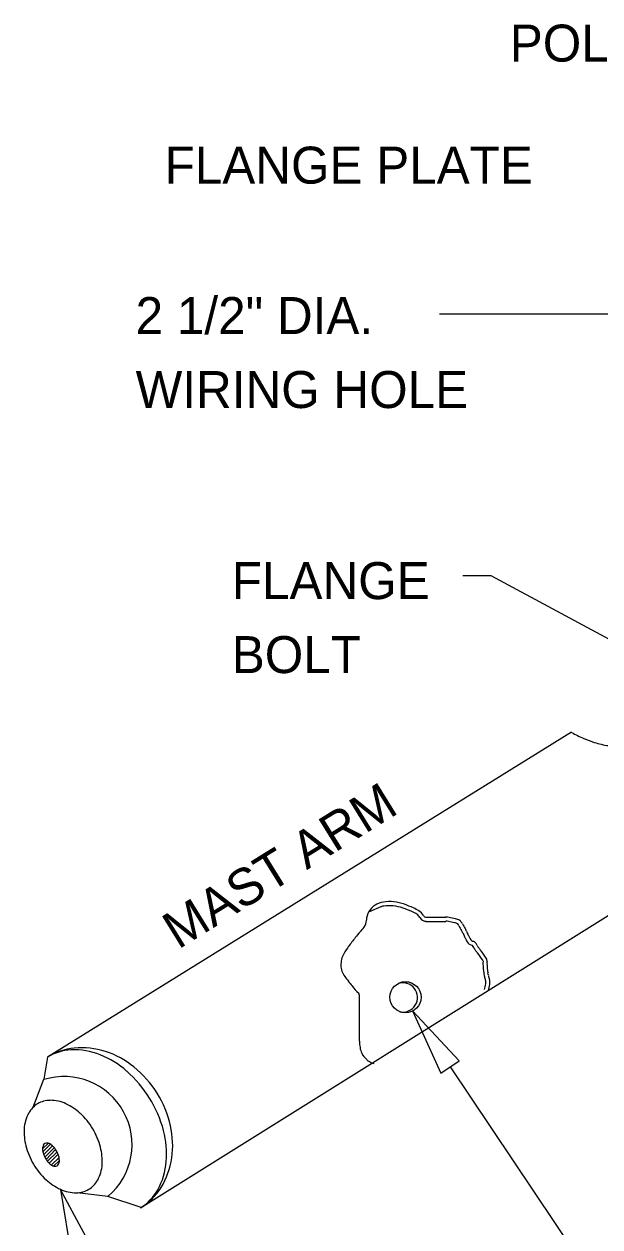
# Model space of a CAD drawing. Extents: x -1551.93 to -1544.71, y 2060.77 to 2070.61.
# Drawn here: x -1550.142 to -1549.207, y 2068.655 to 2070.606 of the extents above; entities that cross this region are included whole.
import ezdxf

# ---------------------------------------------------------------- set-up
doc = ezdxf.new("R2010")
doc.units = 0
for name, color, linetype in [('DETL-DIMS', 7, 'Continuous'), ('DETL-LINE', 7, 'Continuous'), ('DETL-NOTE', 7, 'Continuous')]:
    doc.layers.add(name, color=color, linetype=linetype)

msp = doc.modelspace()

# ---------------------------------------------------------------- linework, layer by layer
at = {"layer": 'DETL-DIMS'}
for p, q in [((-1549.1656, 2070.135), (-1549.4676, 2070.135)), ((-1549.3836, 2069.711), (-1549.4296, 2069.711)), ((-1549.0616, 2069.537), (-1549.3836, 2069.711)), ((-1549.4506, 2068.914), (-1549.2146, 2068.563))]:
    msp.add_line(p, q, dxfattribs=at)
for points in [[(-1549.4656, 2068.904), (-1549.4356, 2068.924), (-1549.5116, 2069.005)], [(-1550.0646, 2068.606), (-1550.0296, 2068.617), (-1550.0826, 2068.715)]]:
    msp.add_lwpolyline(points, close=True, dxfattribs=at)
at = {"layer": 'DETL-LINE'}
for p, q in [((-1549.2536, 2069.457), (-1550.1036, 2068.93)), ((-1549.1096, 2069.212), (-1549.9526, 2068.685)), ((-1549.5626, 2069.174), (-1549.5826, 2069.165)), ((-1550.1036, 2068.93), (-1550.1096, 2068.894)), ((-1550.1266, 2068.849), (-1550.1096, 2068.894)), ((-1550.1116, 2068.781), (-1550.1026, 2068.79)), ((-1550.1116, 2068.776), (-1550.0986, 2068.789)), ((-1550.1096, 2068.772), (-1550.0956, 2068.786)), ((-1550.1076, 2068.768), (-1550.0926, 2068.783)), ((-1550.1056, 2068.764), (-1550.0906, 2068.78)), ((-1550.1036, 2068.761), (-1550.0886, 2068.776)), ((-1550.1006, 2068.758), (-1550.0866, 2068.772)), ((-1550.0976, 2068.755), (-1550.0846, 2068.767)), ((-1550.0936, 2068.753), (-1550.0846, 2068.762)), ((-1550.0056, 2068.704), (-1550.0556, 2068.71)), ((-1549.9516, 2068.686), (-1550.0056, 2068.704))]:
    msp.add_line(p, q, dxfattribs=at)
for points in [[(-1549.4896, 2069.157), (-1549.4726, 2069.157), (-1549.4576, 2069.157)], [(-1549.4896, 2069.15), (-1549.4726, 2069.15), (-1549.4576, 2069.15)], [(-1549.5976, 2068.956), (-1549.5976, 2068.961), (-1549.5976, 2068.98), (-1549.5976, 2068.985), (-1549.5976, 2069.01), (-1549.5976, 2069.031)]]:
    msp.add_lwpolyline(points, dxfattribs=at)
msp.add_circle((-1549.5229, 2069.0271), 0.0253, dxfattribs=at)
for centre, radius, start, end in [((-1549.1315, 2069.6791), 0.2536, 241.2446, 246.3282), ((-1549.1681, 2069.5956), 0.1625, 246.3282, 252.6806), ((-1549.1724, 2069.5817), 0.1479, 252.6806, 261.7135), ((-1549.5542, 2069.149), 0.0328, 123.3386, 148.6731), ((-1549.5537, 2069.1482), 0.0337, 98.3447, 123.3386), ((-1549.5537, 2069.1482), 0.0272, 98.3447, 108.1148), ((-1549.549, 2069.1162), 0.0661, 83.8602, 98.3447), ((-1549.549, 2069.1162), 0.0595, 83.8602, 98.3447), ((-1549.55, 2069.1068), 0.069, 70.3238, 83.8602), ((-1549.55, 2069.1068), 0.0756, 70.3238, 83.8602), ((-1549.5911, 2068.9921), 0.1909, 65.6872, 70.3238), ((-1549.5911, 2068.9921), 0.1974, 65.6872, 70.3238), ((-1549.5419, 2069.1008), 0.0781, 58.3145, 65.6872), ((-1549.6046, 2069.1522), 0.0184, 322.1869, 0.0792), ((-1549.5596, 2069.1523), 0.0265, 148.673, 180.0792), ((-1549.5419, 2069.1008), 0.0716, 58.3145, 65.6872), ((-1549.5119, 2069.1495), 0.0143, 28.9026, 58.3145), ((-1549.5119, 2069.1495), 0.0208, 28.9026, 58.3145), ((-1549.4891, 2069.1621), 0.0118, 208.9026, 270.0637), ((-1549.4891, 2069.1621), 0.00519, 208.9026, 270.0637), ((-1549.4576, 2069.1229), 0.0341, 80.8176, 90.0637), ((-1549.4576, 2069.1229), 0.0275, 80.8176, 90.0637), ((-1549.4726, 2069.03), 0.1215, 76.0538, 80.8176), ((-1549.4726, 2069.03), 0.1281, 76.0538, 80.8176), ((-1549.4516, 2069.1147), 0.0409, 65.4401, 76.0538), ((-1549.4362, 2069.1483), 0.0039, 30.5819, 65.4401), ((-1549.5663, 2069.0714), 0.155, 28.7603, 30.5819), ((-1549.4492, 2068.9998), 0.1987, 137.8117, 141.3618), ((-1549.6934, 2069.2211), 0.1309, 317.8117, 322.1869), ((-1549.4516, 2069.1147), 0.0343, 66.8178, 76.0538), ((-1549.5663, 2069.0714), 0.1485, 28.7603, 30.254), ((-1549.0117, 2069.3758), 0.4842, 208.7603, 209.7981), ((-1547.4275, 2070.283), 2.3098, 209.7981, 209.8596), ((-1549.5096, 2069.0878), 0.091, 29.5607, 29.8596), ((-1549.0117, 2069.3758), 0.4776, 208.7603, 209.7981), ((-1549.4424, 2069.1259), 0.0138, 24.447, 29.5607), ((-1549.1654, 2069.2518), 0.2905, 204.447, 205.8161), ((-1547.4275, 2070.283), 2.3032, 209.7981, 209.8596), ((-1549.5096, 2069.0878), 0.0976, 29.5607, 29.8596), ((-1549.4424, 2069.1259), 0.0204, 24.447, 29.5607), ((-1549.1654, 2069.2518), 0.284, 204.447, 205.8161), ((-1549.3824, 2068.9464), 0.2842, 141.3618, 144.9095), ((-1549.2911, 2069.191), 0.1508, 205.8161, 207.7097), ((-1549.3289, 2069.1711), 0.1082, 207.7097, 209.9657), ((-1549.4124, 2069.123), 0.0118, 209.9657, 259.0294), ((-1549.2911, 2069.191), 0.1443, 205.8161, 207.7097), ((-1549.3289, 2069.1711), 0.1016, 207.7097, 209.9657), ((-1549.4124, 2069.123), 0.00521, 209.9657, 259.0294), ((-1549.4147, 2069.111), 0.000415, 36.9612, 79.0295), ((-1549.434, 2069.0965), 0.0246, 27.5853, 36.9612), ((-1549.4147, 2069.111), 0.00698, 36.9612, 79.0295), ((-1549.434, 2069.0965), 0.0311, 27.5853, 36.9612), ((-1549.5937, 2069.0802), 0.0339, 149.2046, 182.3774), ((-1549.4563, 2068.9983), 0.194, 144.9095, 149.2046), ((-1549.3843, 2069.1224), 0.0315, 207.5853, 218.0695), ((-1549.3264, 2069.1678), 0.1051, 218.0695, 219.1376), ((-1549.5933, 2068.9506), 0.2391, 38.4612, 39.1376), ((-1549.3843, 2069.1224), 0.0249, 207.5853, 218.0695), ((-1549.5332, 2068.9984), 0.1623, 33.1344, 38.4612), ((-1549.3264, 2069.1678), 0.0985, 218.0695, 219.1376), ((-1549.5933, 2068.9506), 0.2456, 38.4612, 39.1376), ((-1549.5332, 2068.9984), 0.1689, 33.1344, 38.4612), ((-1549.5953, 2069.0802), 0.0324, 182.3774, 216.3566), ((-1549.3984, 2069.0864), 0.00127, 8.209, 33.1344), ((-1549.3658, 2069.0825), 0.0314, 174.5747, 183.7608), ((-1549.4018, 2069.0859), 0.00474, 354.5747, 8.209), ((-1549.0562, 2069.1028), 0.3417, 183.7608, 185.4195), ((-1549.3984, 2069.0864), 0.00783, 8.209, 33.1344), ((-1549.3658, 2069.0825), 0.0248, 174.5747, 183.7608), ((-1549.4018, 2069.0859), 0.0113, 354.5747, 8.209), ((-1549.0562, 2069.1028), 0.3352, 183.7608, 185.4195), ((-1549.1773, 2069.3879), 0.5514, 216.3566, 217.3676), ((-1549.1712, 2069.3925), 0.5591, 217.3676, 218.3718), ((-1549.3728, 2069.0728), 0.0236, 185.4195, 192.7739), ((-1549.2287, 2069.1055), 0.1714, 192.7739, 193.6332), ((-1549.8054, 2068.9656), 0.422, 13.1002, 13.6332), ((-1549.4945, 2069.0379), 0.1028, 12.5925, 13.1002), ((-1553.2798, 2068.1923), 3.9814, 12.5084, 12.5925), ((-1549.4104, 2069.0508), 0.0179, 353.7317, 12.5084), ((-1549.3728, 2069.0728), 0.0171, 185.4195, 192.7739), ((-1549.2287, 2069.1055), 0.1649, 192.7739, 193.6332), ((-1549.8054, 2068.9656), 0.4285, 13.1002, 13.6332), ((-1549.4945, 2069.0379), 0.1093, 12.5925, 13.1002), ((-1553.2798, 2068.1923), 3.988, 12.5084, 12.5925), ((-1549.4104, 2069.0508), 0.0244, 353.7317, 12.5084), ((-1549.5152, 2069.1201), 0.1203, 218.3718, 226.0217), ((-1549.6012, 2069.031), 0.00351, 0.0637, 46.0217), ((-1549.5271, 2069.0268), 0.0238, 257.8974, 108.9656), ((-1549.4307, 2069.053), 0.0383, 339.9025, 353.7317), ((-1549.4307, 2069.053), 0.0449, 339.9025, 353.7317), ((-1549.541, 2068.956), 0.0565, 180.0637, 190.7486), ((-1550.0504, 2068.8441), 0.1011, 95.5351, 121.8896), ((-1550.0622, 2068.8628), 0.079, 92.4256, 121.7773), ((-1550.0607, 2068.8271), 0.1148, 68.1513, 92.4256), ((-1550.0482, 2068.8212), 0.1241, 71.7884, 95.5351), ((-1550.0547, 2068.8015), 0.145, 50.9917, 71.7884), ((-1549.5512, 2068.9541), 0.0462, 190.7486, 202.5708), ((-1549.5803, 2068.942), 0.0147, 202.5708, 218.2209), ((-1550.0734, 2068.7953), 0.149, 48.7439, 68.1513), ((-1549.5306, 2068.9812), 0.078, 218.2209, 224.9986), ((-1549.5704, 2068.9414), 0.0217, 224.9986, 239.9223), ((-1549.5609, 2068.9578), 0.0406, 239.9223, 250.8096), ((-1550.0768, 2068.7882), 0.1104, 310.5048, 107.201), ((-1550.1034, 2068.7611), 0.1946, 31.7773, 48.7439), ((-1550.0714, 2068.7808), 0.1715, 31.8896, 50.9917), ((-1550.0995, 2068.8207), 0.0392, 89.8741, 120.8478), ((-1550.0996, 2068.7974), 0.0626, 65.4568, 89.8741), ((-1550.1034, 2068.7611), 0.1946, 14.8107, 31.7773), ((-1550.0714, 2068.7808), 0.1715, 12.7876, 31.8896), ((-1550.079, 2068.8097), 0.0626, 151.8216, 176.2389), ((-1550.0995, 2068.8207), 0.0392, 120.8478, 151.8216), ((-1550.1092, 2068.7764), 0.0856, 46.8, 65.4568), ((-1550.1305, 2068.7537), 0.1169, 30.8478, 46.8), ((-1550.0455, 2068.7867), 0.145, 351.9909, 12.7876), ((-1550.0559, 2068.8082), 0.0856, 176.2389, 194.8957), ((-1550.1305, 2068.7537), 0.1169, 14.8957, 30.8478), ((-1550.0594, 2068.7727), 0.149, 355.4034, 14.8107), ((-1550.0258, 2068.8162), 0.1169, 194.8957, 210.8478), ((-1550.0966, 2068.7814), 0.0149, 156.9296, 180.889), ((-1550.0864, 2068.7815), 0.0252, 180.889, 196.1399), ((-1550.105, 2068.7849), 0.00586, 118.2262, 156.9296), ((-1550.105, 2068.7849), 0.00586, 79.5228, 118.2262), ((-1550.1066, 2068.776), 0.0149, 55.5634, 79.5228), ((-1550.1124, 2068.7675), 0.0252, 40.3126, 55.5634), ((-1550.1237, 2068.7579), 0.04, 28.2262, 40.3126), ((-1550.1004, 2068.7617), 0.0856, 356.2389, 14.8957), ((-1550.0721, 2068.7857), 0.04, 196.1399, 208.2262), ((-1550.0721, 2068.7857), 0.04, 208.2262, 220.3126), ((-1550.0834, 2068.7761), 0.0252, 220.3126, 235.5634), ((-1550.1237, 2068.7579), 0.04, 16.1399, 28.2262), ((-1550.0992, 2068.7622), 0.0149, 336.9296, 0.889), ((-1550.1095, 2068.7621), 0.0252, 0.889, 16.1399), ((-1550.0253, 2068.77), 0.1148, 331.129, 355.4034), ((-1550.0249, 2068.7838), 0.1241, 328.2442, 351.9909), ((-1550.0258, 2068.8162), 0.1169, 210.8478, 226.8), ((-1550.0892, 2068.7676), 0.0149, 235.5634, 259.5228), ((-1550.0909, 2068.7587), 0.00586, 259.5228, 298.2262), ((-1550.0909, 2068.7587), 0.00586, 298.2262, 336.9296), ((-1550.0773, 2068.7602), 0.0626, 331.8216, 356.2389), ((-1550.0471, 2068.7935), 0.0856, 226.8, 245.4568), ((-1550.0568, 2068.7492), 0.0392, 300.8478, 331.8216), ((-1550.0567, 2068.7725), 0.0626, 245.4568, 269.8741), ((-1550.0568, 2068.7492), 0.0392, 269.8741, 300.8478), ((-1549.994, 2068.7527), 0.079, 301.7773, 331.129), ((-1550.0053, 2068.7717), 0.1011, 301.8896, 328.2442), ((-1550.0053, 2068.7717), 0.1011, 301.5702, 301.8896)]:
    msp.add_arc(centre, radius, start, end, dxfattribs=at)

# ---------------------------------------------------------------- texts
at = {"layer": 'DETL-NOTE'}
for s, p in [('POLE CAP', (-1549.3536, 2070.545)), ('FLANGE PLATE', (-1549.9136, 2070.347)), ('2 1/2" DIA.', (-1549.9606, 2070.103)), ('WIRING HOLE', (-1549.9606, 2069.983)), ('FLANGE', (-1549.8046, 2069.673)), ('BOLT', (-1549.8046, 2069.553))]:
    msp.add_text(s, height=0.06, dxfattribs=at).set_placement(p)
msp.add_text('MAST ARM', height=0.06, rotation=31.7773, dxfattribs=at).set_placement((-1549.8916, 2069.104))

doc.saveas('drawing.dxf')
